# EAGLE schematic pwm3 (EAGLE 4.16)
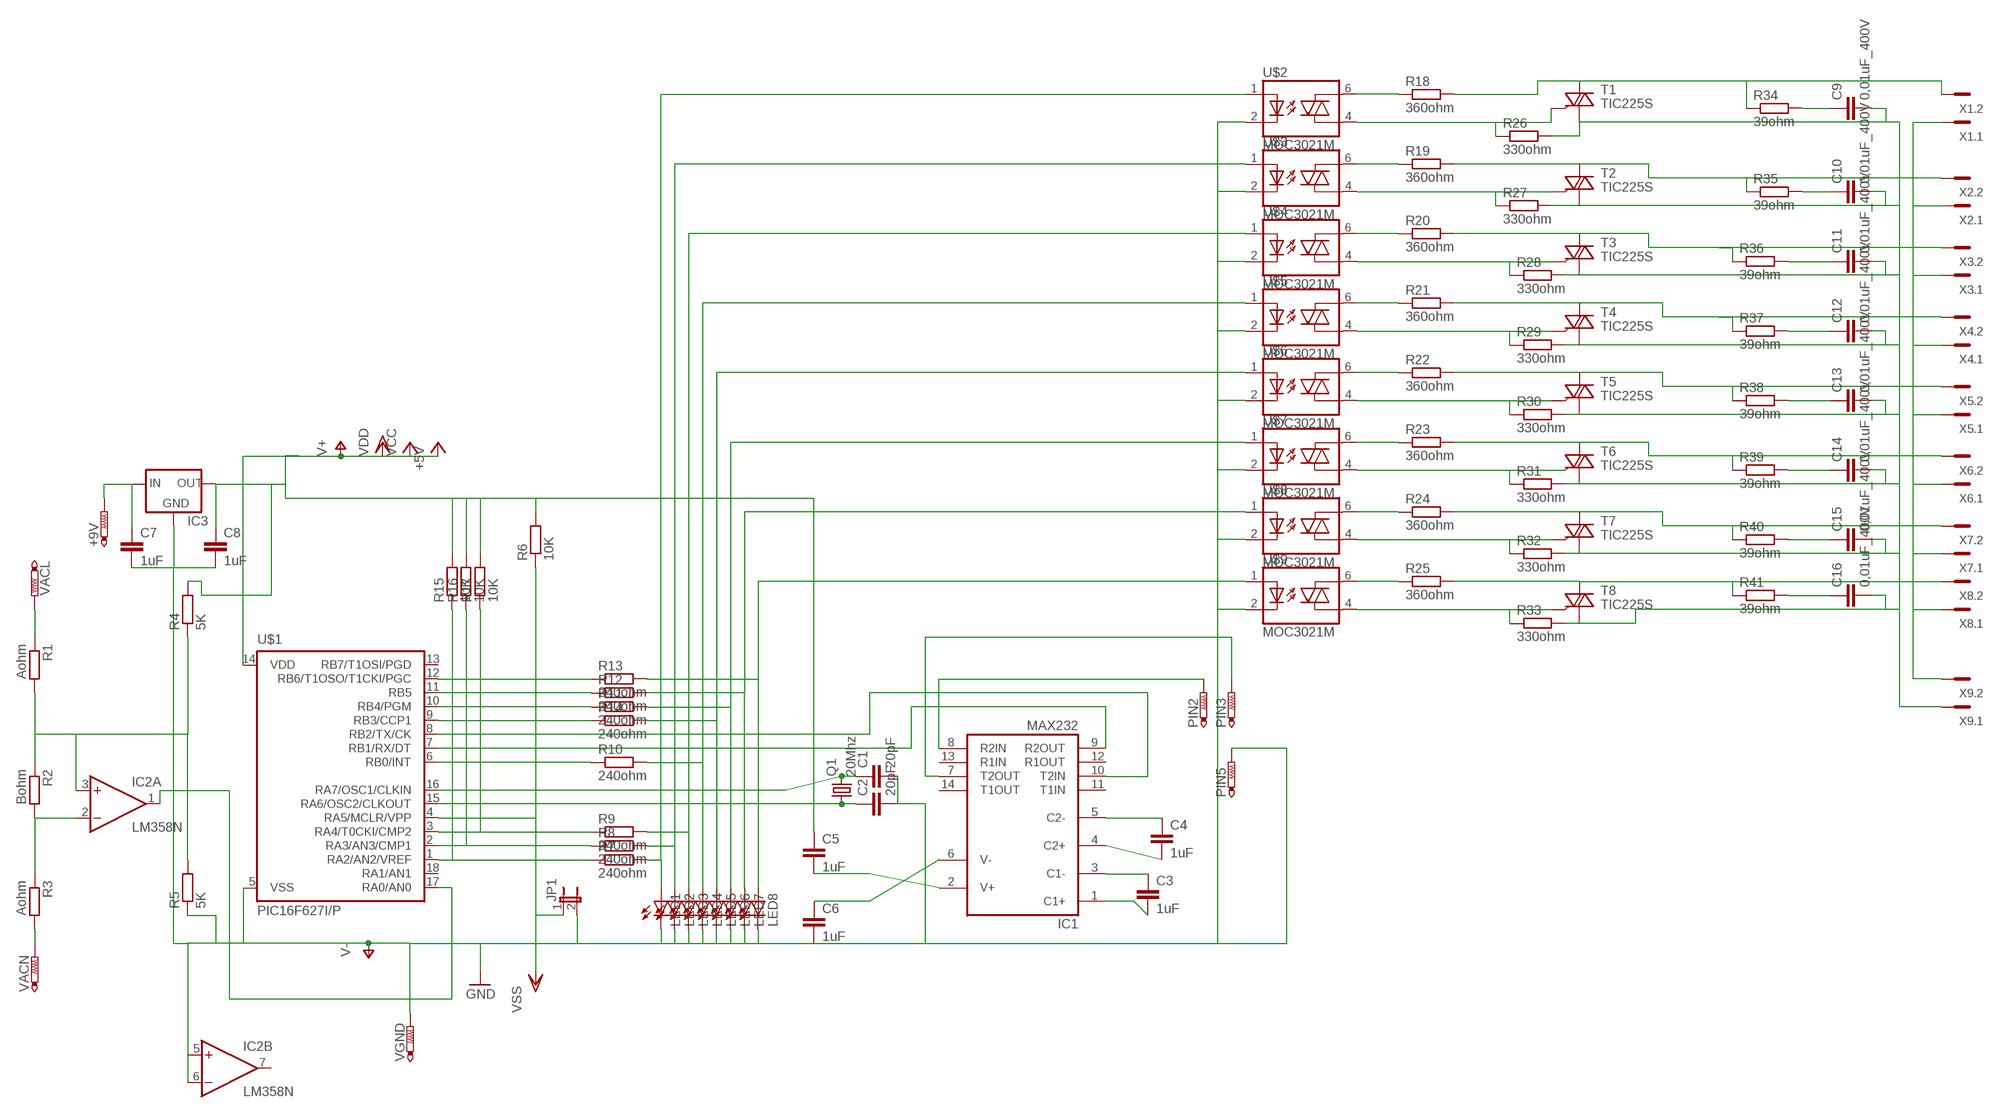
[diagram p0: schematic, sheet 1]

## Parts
+9V  PTR1PAD1-13  [P1-13]
C1  20pF  C-EU075-032X103  [C075-032X103]
C2  20pF  C-EU075-032X103  [C075-032X103]
C3  1uF  C-EU050-025X075  [C050-025X075]
C4  1uF  C-EU050-025X075  [C050-025X075]
C5  1uF  C-EU075-032X103  [C075-032X103]
C6  1uF  C-EU075-032X103  [C075-032X103]
C7  1uF  C-EU075-032X103  [C075-032X103]
C8  1uF  C-EU075-032X103  [C075-032X103]
C9  0,01uF_400V  C-EU050-025X075  [C050-025X075]
C10  0,01uF_400V  C-EU050-025X075  [C050-025X075]
C11  0,01uF_400V  C-EU050-025X075  [C050-025X075]
C12  0,01uF_400V  C-EU050-025X075  [C050-025X075]
C13  0,01uF_400V  C-EU050-025X075  [C050-025X075]
C14  0,01uF_400V  C-EU050-025X075  [C050-025X075]
C15  0,01uF_400V  C-EU050-025X075  [C050-025X075]
C16  0,01uF_400V  C-EU050-025X075  [C050-025X075]
IC1  MAX232  [DIL16]
IC2  LM358N  [DIL08]
IC3  78XXL  [78XXL]
JP1  JP1E  [JP1]
LED1  LED5MM  [LED5MM]
LED2  LED5MM  [LED5MM]
LED3  LED5MM  [LED5MM]
LED4  LED5MM  [LED5MM]
LED5  LED5MM  [LED5MM]
LED6  LED5MM  [LED5MM]
LED7  LED5MM  [LED5MM]
LED8  LED5MM  [LED5MM]
PIN2  PTR1PAD1-13  [P1-13]
PIN3  PTR1PAD1-13  [P1-13]
PIN5  PTR1PAD1-13  [P1-13]
Q1  20Mhz  CRYSTALHC18U-V  [HC18U-V]
R1  Aohm  R-EU_0207/10  [0207/10]
R2  Bohm  R-EU_0204/2V  [0204V]
R3  Aohm  R-EU_0207/10  [0207/10]
R4  5K  R-EU_0207/10  [0207/10]
R5  5K  R-EU_0204/2V  [0204V]
R6  10K  R-EU_0204/7  [0204/7]
R7  240ohm  R-EU_0207/7  [0207/7]
R8  240ohm  R-EU_0207/7  [0207/7]
R9  240ohm  R-EU_0207/7  [0207/7]
R10  240ohm  R-EU_0207/7  [0207/7]
R11  240ohm  R-EU_0207/7  [0207/7]
R12  240ohm  R-EU_0207/7  [0207/7]
R13  240ohm  R-EU_0207/7  [0207/7]
R14  240ohm  R-EU_0207/7  [0207/7]
R15  10K  R-EU_0204/7  [0204/7]
R16  10K  R-EU_0204/7  [0204/7]
R17  10K  R-EU_0204/7  [0204/7]
R18  360ohm  R-EU_0204/7  [0204/7]
R19  360ohm  R-EU_0204/7  [0204/7]
R20  360ohm  R-EU_0204/7  [0204/7]
R21  360ohm  R-EU_0204/7  [0204/7]
R22  360ohm  R-EU_0204/7  [0204/7]
R23  360ohm  R-EU_0204/7  [0204/7]
R24  360ohm  R-EU_0204/7  [0204/7]
R25  360ohm  R-EU_0204/7  [0204/7]
R26  330ohm  R-EU_0207/7  [0207/7]
R27  330ohm  R-EU_0207/7  [0207/7]
R28  330ohm  R-EU_0207/7  [0207/7]
R29  330ohm  R-EU_0207/7  [0207/7]
R30  330ohm  R-EU_0207/7  [0207/7]
R31  330ohm  R-EU_0207/7  [0207/7]
R32  330ohm  R-EU_0207/7  [0207/7]
R33  330ohm  R-EU_0207/7  [0207/7]
R34  39ohm  R-EU_0207/7  [0207/7]
R35  39ohm  R-EU_0207/7  [0207/7]
R36  39ohm  R-EU_0207/7  [0207/7]
R37  39ohm  R-EU_0207/7  [0207/7]
R38  39ohm  R-EU_0207/7  [0207/7]
R39  39ohm  R-EU_0207/7  [0207/7]
R40  39ohm  R-EU_0207/7  [0207/7]
R41  39ohm  R-EU_0207/7  [0207/7]
T1  TIC225S  [TO220DS]
T2  TIC225S  [TO220DS]
T3  TIC225S  [TO220DS]
T4  TIC225S  [TO220DS]
T5  TIC225S  [TO220DS]
T6  TIC225S  [TO220DS]
T7  TIC225S  [TO220DS]
T8  TIC225S  [TO220DS]
U$1  PIC16F627I/P  [DIL18]
U$2  MOC3021M  [DIL06]
U$3  MOC3021M  [DIL06]
U$4  MOC3021M  [DIL06]
U$5  MOC3021M  [DIL06]
U$6  MOC3021M  [DIL06]
U$7  MOC3021M  [DIL06]
U$8  MOC3021M  [DIL06]
U$9  MOC3021M  [DIL06]
VACL  PTR1PAD1-13  [P1-13]
VACN  PTR1PAD1-13  [P1-13]
VGND  PTR1PAD1-13  [P1-13]
X1  MCV2  [MCV2]
X2  MCV2  [MCV2]
X3  MCV2  [MCV2]
X4  MCV2  [MCV2]
X5  MCV2  [MCV2]
X6  MCV2  [MCV2]
X7  MCV2  [MCV2]
X8  MCV2  [MCV2]
X9  MCV2  [MCV2]

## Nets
N$1: C1.1 Q1.2 U$1.16(RA7/OSC1/CLKIN)
N$2: C2.1 Q1.1 U$1.15(RA6/OSC2/CLKOUT)
N$3: +9V.1(TP) C7.1 IC3.IN
N$4: C4.1 IC1.5(C2-)
N$5: C4.2 IC1.4(C2+)
N$6: C3.1 IC1.3(C1-)
N$7: C3.2 IC1.1(C1+)
N$8: C5.2 IC1.2(V+)
N$9: C6.1 IC1.6(V-)
N$10: R7.1 R15.1 U$1.1(RA2/AN2/VREF)
N$11: IC2.2(A:-IN) R2.2 R3.1
N$12: IC2.1(A:OUT) U$1.17(RA0/AN0)
N$13: IC2.3(A:+IN) R1.2 R2.1 R4.1 R5.2
N$14: IC1.9(R2OUT) U$1.7(RB1/RX/DT)
N$15: IC1.10(T2IN) U$1.8(RB2/TX/CK)
N$16: R1.1 VACL.1(TP)
N$17: R3.2 VACN.1(TP)
N$18: R8.1 R16.1 U$1.2(RA3/AN3/CMP1)
N$19: R9.1 R17.1 U$1.3(RA4/T0CKI/CMP2)
N$20: IC1.8(R2IN) PIN2.1(TP)
N$21: IC1.7(T2OUT) PIN3.1(TP)
N$22: R10.1 U$1.6(RB0/INT)
N$23: R14.1 U$1.9(RB3/CCP1)
N$24: R11.1 U$1.10(RB4/PGM)
N$25: R12.1 U$1.11(RB5)
N$26: R13.1 U$1.12(RB6/T1OSO/T1CKI/PGC)
N$27: LED1.A R7.2 U$2.1(A)
N$28: LED2.A R8.2 U$3.1(A)
N$29: LED3.A R9.2 U$4.1(A)
N$30: LED4.A R10.2 U$5.1(A)
N$31: LED5.A R14.2 U$6.1(A)
N$32: LED6.A R11.2 U$7.1(A)
N$33: LED7.A R12.2 U$8.1(A)
N$34: LED8.A R13.2 U$9.1(A)
N$35: X1.1 X2.1 X3.1 X4.1 X5.1 X6.1 X7.1 X8.1 X9.2
N$37: C9.1 R34.2
N$38: R18.1 U$2.6(A2)
N$39: R19.1 U$3.6(A2)
N$40: R20.1 U$4.6(A2)
N$41: R21.1 U$5.6(A2)
N$42: R22.1 U$6.6(A2)
N$43: R23.1 U$7.6(A2)
N$44: R24.1 U$8.6(A2)
N$45: R25.1 U$9.6(A2)
N$46: R18.2 R34.1 T1.A2 X1.2
N$47: R19.2 R35.1 T2.A2 X2.2
N$48: R20.2 R36.1 T3.A2 X3.2
N$49: R21.2 R37.1 T4.A2 X4.2
N$50: R22.2 R38.1 T5.A2 X5.2
N$51: R23.2 R39.1 T6.A2 X6.2
N$52: R24.2 R40.1 T7.A2 X7.2
N$53: R25.2 R41.1 T8.A2 X8.2
N$54: R26.1 T1.G U$2.4(A1)
N$55: R27.1 T2.G U$3.4(A1)
N$56: R28.1 T3.G U$4.4(A1)
N$57: R29.1 T4.G U$5.4(A1)
N$58: R30.1 T5.G U$6.4(A1)
N$59: R31.1 U$7.4(A1)
N$60: R32.1 T7.G U$8.4(A1)
N$61: R33.1 T8.G U$9.4(A1)
N$62: C9.2 C10.2 C11.2 C12.2 C13.2 C14.2 C15.2 C16.2 R26.2 R27.2 R28.2 R29.2 R30.2 R31.2 R32.2 R33.2 T1.A1 T2.A1 T3.A1 T4.A1 T5.A1 T6.A1 T7.A1 T8.A1 X9.1
N$70: C10.1 R35.2
N$71: C11.1 R36.2
N$72: C12.1 R37.2
N$73: C13.1 R38.2
N$74: C14.1 R39.2
N$75: C15.1 R40.2
N$76: C16.1 R41.2
V+: C5.1 C8.1 IC3.OUT R4.2 R6.2 R15.2 R16.2 R17.2 U$1.14(VDD) ; supply symbol labelled +5V, VCC, VDD
V-: C1.2 C2.2 C6.2 C7.2 C8.2 IC2.5(B:+IN) IC2.6(B:-IN) IC3.GND JP1.1 JP1.2 LED1.K(C) LED2.K(C) LED3.K(C) LED4.K(C) LED5.K(C) LED6.K(C) LED7.K(C) LED8.K(C) PIN5.1(TP) R5.1 R6.1 U$1.4(RA5/MCLR/VPP) U$1.5(VSS) U$2.2(C) U$3.2(C) U$4.2(C) U$5.2(C) U$6.2(C) U$7.2(C) U$8.2(C) U$9.2(C) VGND.1(TP) ; supply symbol labelled GND, VSS
Unconnected: IC1.11(T1IN) IC1.12(R1OUT) IC1.13(R1IN) IC1.14(T1OUT) IC2.7(B:OUT) T6.G U$1.13(RB7/T1OSI/PGD) U$1.18(RA1/AN1)

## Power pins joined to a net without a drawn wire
GND: IC1.15(GND)
V+: IC2.8(P:V+)
V-: IC2.4(P:V-)
VCC: IC1.16(VCC)

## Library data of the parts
+9V PIN2 PIN3 PIN5 VACL VACN VGND = testpad:PTR1: TEST PIN
C1-C16 = rcl:C-EU: CAPACITOR, European symbol
IC1 = maxim:MAX232: RS232 TRANSEIVER
IC2 = linear:LM358: OP AMP also LM158; LM258; LM2904 Source: http://cache.national.com/ds/LM/LM158.pdf
IC3 = v-reg:78XXL: VOLTAGE REGULATOR
JP1 = jumper:JP1E: JUMPER
LED1-LED8 = led:LED: LED
Q1 = crystal:CRYSTAL: CRYSTAL
R1-R41 = rcl:R-EU_: RESISTOR, European symbol
T1-T8 = triac:TIC225S: TRIAC
U$1 = microchip-4:PIC16F627*: MICROCONTROLLER PIC16F627(A) 16 I/O One 16-bit timer (TMR0) Two 8-bit timer (TMR0) Two comparators USART CCP/PWM Precision 4 MHz internal oscillator 1k Program Flash memory 224 bytes SRAM 128 bytes EEPROM
U$2-U$9 = optocoupler:MOC30*M: RANDOM-PHASE OPTOISOLATORS TRIAC DRIVER OUTPUT Source: http://www.fairchildsemi.com MOC3020-M.pdf
X1-X9 = con-phoenix-381_l:MCV2: Mini-Combicon 3.81mm vertikal 2polig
